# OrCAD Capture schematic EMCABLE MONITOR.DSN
size B; title: EM Cable Simple Monitor; note: NA
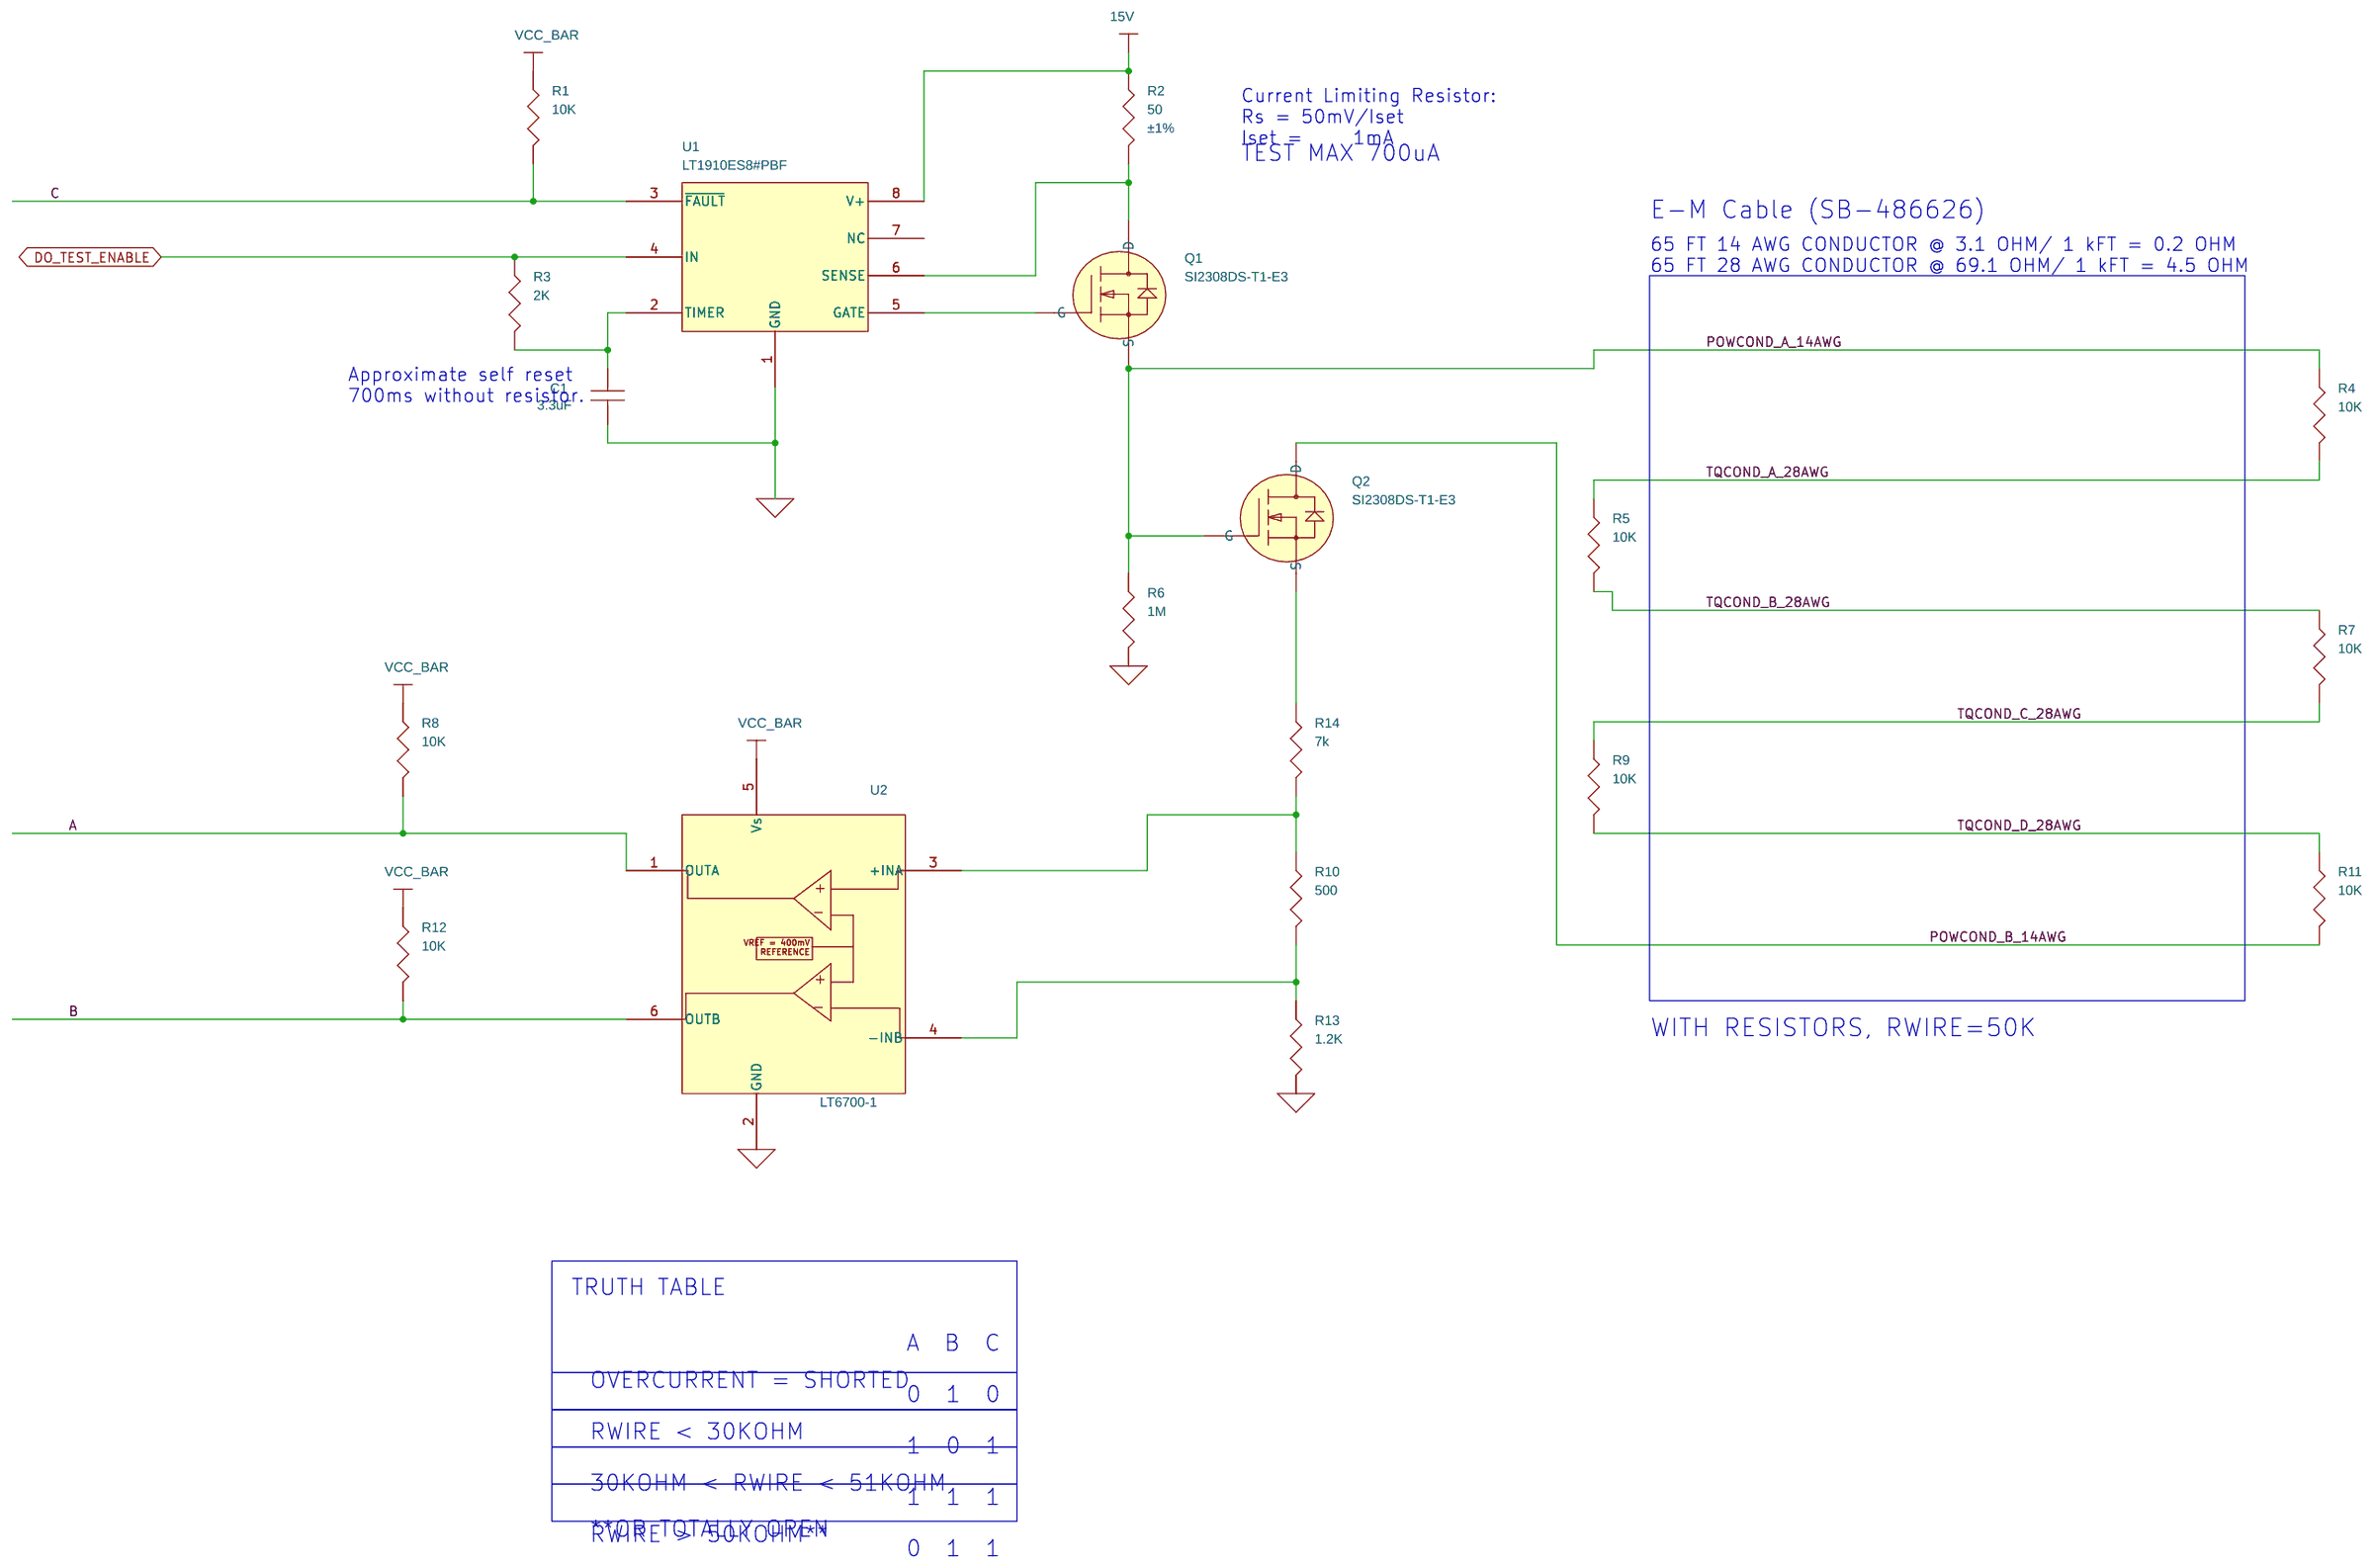
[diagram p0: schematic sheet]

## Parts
C1  3.3uF
Q1  SI2308DS-T1-E3  [SOT95P237X112-3N_132]
Q2  SI2308DS-T1-E3  [SOT95P237X112-3N_132]
R1  10K
R2  50  [RESC3116X65N]
R3  2K
R4  10K
R5  10K
R6  1M
R7  10K
R8  10K
R9  10K
R10  500
R11  10K
R12  10K
R13  1.2K
R14  7k
U1  LT1910ES8#PBF  [SOIC127P599X175-8L86N]
U2  LT6700-1

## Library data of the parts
C1 = CAP
Q1 Q2 = MOSFET_I_EN_GSD: MOSFET N-CH 60V 2A SOT23-3; CLASS: DISCRETE; Manufacturer: Vishay/Siliconix; Package Size: SOT-23-3, TO-236-3, Micro3â„¢, SSD3, SST3; Rated Power: 1.25W
R1 R3-R14 = RES
R2 = RES: RES .05 OHM 1/2W 1% 1206 SMD; CLASS: DISCRETE; Manufacturer: Stackpole Electronics Inc; Manufacturer PN: CSR1206FK50L0; PART_NUMBER: CSR1206FK50L0; Package Size: 1206 (3216 Metric); Rated Power: 0.5W, 1/2W; Temperature Coefficient: ±100ppm/°C; Tolerance: ±1%
U1 = LT1910: IC MOSFET DRIVER HIGH-SIDE 8SOIC; CLASS: DISCRETE; Manufacturer: Linear Technology; Package Size: 8-SOIC (0.154", 3.90mm Width)
U2 = LT6700-1

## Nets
3.3V: R1.1 R8.1 R12.1
15V: R2.1 U1.8(V+) U2.5(Vs)
GND_SIGNAL: C1.2 R6.2 R13.2 U1.1(GND) U2.2(GND)
A: R8.2 U2.1(OUTA)
B: R12.2 U2.6(OUTB)
C: R1.2 U1.3(~{FAULT})
DO_TEST_ENABLE: R3.1 U1.4(IN)
POWCOND_A_14AWG: Q1.2(S) Q2.1(G) R4.1 R6.1
POWCOND_B_14AWG: Q2.3(D) R11.2
TQCOND_A_28AWG: R4.2 R5.1
TQCOND_B_28AWG: R5.2 R7.1
TQCOND_C_28AWG: R7.2 R9.1
TQCOND_D_28AWG: R9.2 R11.1
N103024: Q1.1(G) U1.5(GATE)
N103048: Q1.3(D) R2.2 U1.6(SENSE)
N103132: C1.1 R3.2 U1.2(TIMER)
N106807: R10.2 R13.1 U2.4(-INB)
N107716: Q2.2(S) R14.1
N107720: R10.1 R14.2 U2.3(+INA)

Not connected (* = marked no-connect by the designer): U1 7(NC)

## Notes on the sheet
- Current Limiting Resistor:
  Rs = 50mV/Iset
  Iset =     1mA
- TEST MAX 700uA
- E-M Cable (SB-486626)
- 65 FT 14 AWG CONDUCTOR @ 3.1 OHM/ 1 kFT = 0.2 OHM
  65 FT 28 AWG CONDUCTOR @ 69.1 OHM/ 1 kFT = 4.5 OHM
- Approximate self reset
  700ms without resistor.
- WITH RESISTORS, RWIRE=50K
- TRUTH TABLE
- A  B  C
  0  1  0
  1  0  1
  1  1  1
  0  1  1
- OVERCURRENT = SHORTED
  RWIRE < 30KOHM
  30KOHM < RWIRE < 51KOHM
  RWIRE > 50KOHM**
- **OR TOTALLY OPEN
